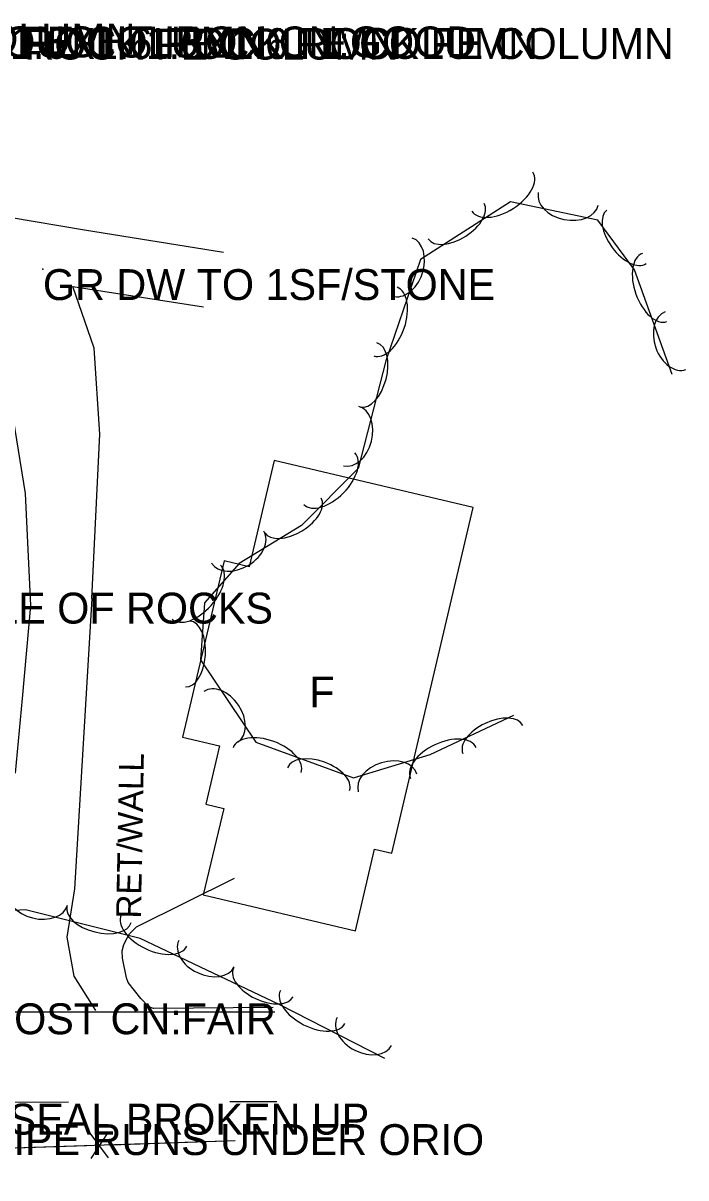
# Model space of a CAD drawing. Extents: x 954793 to 988390, y 1867850 to 1924428.
# Drawn here: x 961164.2 to 961271.4, y 1905548.4 to 1905735.2 of the extents above; entities that cross this region are included whole.
import ezdxf

# ---------------------------------------------------------------- set-up
doc = ezdxf.new("R2010")
doc.units = 0
for name, color, linetype in [('S_BUILDING', 7, 'Continuous'), ('S_BUILDING_ANNOT', 7, 'Continuous'), ('S_DRIVEWAY', 7, 'Continuous'), ('S_FENCE', 7, 'Continuous'), ('S_GRAVEL_ROAD', 7, 'Continuous'), ('S_IRON_PIN_ANNOT', 7, 'Continuous'), ('S_MSC_PT_SYM', 7, 'Continuous'), ('S_SIDE_DRAIN_ANNOT', 7, 'Continuous'), ('S_SURVEY_TEXT_ANNOT', 7, 'Continuous'), ('S_TREE', 7, 'Continuous'), ('S_WALL_ANNOT', 7, 'Continuous')]:
    doc.layers.add(name, color=color, linetype=linetype)

msp = doc.modelspace()

# ---------------------------------------------------------------- linework, layer by layer
at = {"layer": 'S_BUILDING'}
msp.add_lwpolyline([(961223.83, 1905600.9), (961237.02, 1905656.83), (961204.78, 1905664.44), (961200.73, 1905647.26), (961196.7, 1905648.21), (961189.97, 1905619.69), (961195.95, 1905618.28), (961193.73, 1905608.83), (961196.63, 1905608.14), (961193.33, 1905594.15), (961217.95, 1905588.35), (961221.06, 1905601.55)], close=True, dxfattribs=at)
at = {"layer": 'S_DRIVEWAY'}
for points in [[(961196.58, 1905698.09), (961174.09, 1905701.72), (961161.98, 1905703.77), (961149.81, 1905709.09), (961137.67, 1905715.2)], [(961135.97, 1905706.65), (961153.47, 1905696.04), (961160.56, 1905683.46), (961164.51, 1905659.13), (961165.37, 1905640.98), (961164, 1905625.93), (961162.9, 1905613.85)], [(961175.28, 1905642.09), (961175.94, 1905655.4), (961176.61, 1905668.72), (961175.68, 1905682.63), (961172.21, 1905692.58), (961193.35, 1905689.33)], [(961175.28, 1905642.09), (961172.49, 1905595.13), (961171.22, 1905587.33), (961172.38, 1905581.01), (961175.86, 1905575.43)]]:
    msp.add_lwpolyline(points, dxfattribs=at)
at = {"layer": 'S_FENCE'}
for p, q in [((961178, 1905551.6), (961175, 1905555.6)), ((961177.86, 1905555.7), (961175.13, 1905551.51))]:
    msp.add_line(p, q, dxfattribs=at)
for points in [[(961198.49, 1905554.33), (961040.37, 1905549.11)], [(961174.5, 1905553.54), (961154.51, 1905552.88)], [(961198.49, 1905554.33), (961178.5, 1905553.67)]]:
    msp.add_lwpolyline(points, dxfattribs=at)
at = {"layer": 'S_GRAVEL_ROAD'}
for points in [[(961028.96, 1905573.17), (961049.1, 1905571.96), (961076.77, 1905571.9), (961120.25, 1905573.73), (961159.89, 1905575.21), (961204.9, 1905575.25)], [(961205.25, 1905560.69), (961197.61, 1905560.67)], [(961171.5, 1905560.59), (961140.67, 1905560.5), (961110.89, 1905559.04), (961064.17, 1905555.68), (961043.24, 1905554.69), (961020.94, 1905553.02), (961010.77, 1905548.35)]]:
    msp.add_lwpolyline(points, dxfattribs=at)
at = {"layer": 'S_IRON_PIN_ANNOT'}
msp.add_lwpolyline([(961204.64, 1905575.93), (961185.25, 1905575.79), (961184.53, 1905576.03), (961183.22, 1905577.37), (961181.16, 1905579.97), (961180.91, 1905580.71), (961180.26, 1905583.91), (961180.21, 1905585.12), (961180.49, 1905586.11), (961181.04, 1905587.23), (961181.38, 1905587.83), (961181.85, 1905588.34), (961182.52, 1905588.99), (961198.4, 1905596.88)], dxfattribs=at)
at = {"layer": 'S_MSC_PT_SYM'}
for points in [[(961184.01, 1905734.41), (961184.01, 1905734.46), (961184.01, 1905734.41), (961183.96, 1905734.41), (961184.01, 1905734.41), (961184.01, 1905734.36), (961184.01, 1905734.41), (961184.06, 1905734.41)], [(961184.01, 1905734.41), (961184.01, 1905734.46), (961184.01, 1905734.41), (961183.96, 1905734.41), (961184.01, 1905734.41), (961184.01, 1905734.36), (961184.01, 1905734.41), (961184.06, 1905734.41)], [(961167.38, 1905695.41), (961167.38, 1905695.46), (961167.38, 1905695.41), (961167.33, 1905695.41), (961167.38, 1905695.41), (961167.38, 1905695.36), (961167.38, 1905695.41), (961167.43, 1905695.41)], [(961167.38, 1905695.41), (961167.38, 1905695.46), (961167.38, 1905695.41), (961167.33, 1905695.41), (961167.38, 1905695.41), (961167.38, 1905695.36), (961167.38, 1905695.41), (961167.43, 1905695.41)]]:
    msp.add_lwpolyline(points, close=True, dxfattribs=at)
for points in [[(961184.01, 1905734.41), (961184.01, 1905734.46), (961184.01, 1905734.41), (961183.96, 1905734.41), (961184.01, 1905734.41), (961184.01, 1905734.36), (961184.01, 1905734.41), (961184.06, 1905734.41)], [(961167.38, 1905695.41), (961167.38, 1905695.46), (961167.38, 1905695.41), (961167.33, 1905695.41), (961167.38, 1905695.41), (961167.38, 1905695.36), (961167.38, 1905695.41), (961167.43, 1905695.41)]]:
    msp.add_lwpolyline(points, dxfattribs=at)
at = {"layer": 'S_TREE'}
for points in [[(961269.19, 1905678.35), (961263.1, 1905695.31), (961257.16, 1905703.35), (961243.06, 1905706.29), (961228.47, 1905696.99), (961222.87, 1905680.56), (961218.37, 1905663.17), (961209.23, 1905653.92), (961199.14, 1905647.76), (961193.5, 1905641.42), (961192.87, 1905632.2), (961201.82, 1905618.87), (961217.62, 1905613.1), (961230.04, 1905616.85), (961243.6, 1905623.25)], [(961222.72, 1905567.66), (961205.71, 1905576.35), (961183.12, 1905587.1), (961164.56, 1905591.76), (961147.02, 1905590.73)]]:
    msp.add_lwpolyline(points, dxfattribs=at)
for centre, major_axis, ratio in [((961241.73, 1905707.95), (4.95, 3.15), 0.55008), ((961252.39, 1905706.78), (4.85, -1.01), 0.685311), ((961234.25, 1905703.18), (4.51, 2.87), 0.540699), ((961261.8, 1905700.64), (3.18, -4.3), 0.540699), ((961225.54, 1905695.76), (1.6, 4.69), 0.685311), ((961266.38, 1905692.45), (1.98, -5.52), 0.55008), ((961222.8, 1905686.92), (1.89, 5.55), 0.55008), ((961269.76, 1905683.82), (1.68, -4.66), 0.685311), ((961220.1, 1905678.31), (1.34, 5.18), 0.540699), ((961217.26, 1905668.4), (1.24, 4.8), 0.685311), ((961213.72, 1905661.48), (4.12, 4.18), 0.55008), ((961207.84, 1905655.55), (4.56, 2.79), 0.540699), ((961198.91, 1905650.41), (4.23, 2.58), 0.685311), ((961192.19, 1905643.14), (3.9, 4.38), 0.55008), ((961190.8, 1905633.13), (0.37, 5.33), 0.540699), ((961196.2, 1905622.97), (-2.76, 4.11), 0.685311), ((961240.19, 1905619.29), (-4.84, -2.28), 0.540699), ((961203.65, 1905615.94), (-5.51, 2.01), 0.55008), ((961232.17, 1905615.51), (-5.31, -2.5), 0.55008), ((961211.98, 1905612.9), (-5.02, 1.83), 0.540699), ((961223.16, 1905612.28), (-4.74, -1.43), 0.685311), ((961166.53, 1905593.72), (4.81, -1.21), 0.685311), ((961176.46, 1905590.96), (5.19, -1.3), 0.540699), ((961185.36, 1905588.38), (5.3, -2.52), 0.55008), ((961193.83, 1905584.64), (4.48, -2.13), 0.685311), ((961203.03, 1905579.98), (4.83, -2.3), 0.540699), ((961211.03, 1905576.02), (5.22, -2.67), 0.55008), ((961219.39, 1905572.04), (4.41, -2.26), 0.685311)]:
    msp.add_ellipse(centre, major_axis=major_axis, ratio=ratio, start_param=3.141593, end_param=6.283185, dxfattribs=at)

# ---------------------------------------------------------------- texts
at = {"layer": 'S_BUILDING_ANNOT'}
msp.add_text('F', height=5, dxfattribs=at).set_placement((961210.48, 1905624.49))
at = {"layer": 'S_SIDE_DRAIN_ANNOT'}
msp.add_text('CN:5% FILL PIPE RUNS UNDER ORIO', height=5, dxfattribs=at).set_placement((961119.89, 1905552.05))
at = {"layer": 'S_SURVEY_TEXT_ANNOT'}
for s, p in [('1.6X1.6 ROCK FE COLUMN', (961096.88, 1905730.15)), ('1.6X1.6 ROCK FE COLUMN', (961117.82, 1905729.65)), ('FE-4.0 WROUGHT IRON CN:GOOD', (961127.9, 1905729.68)), ('1.6X1.6 ROCK FE COLUMN', (961139.47, 1905729.33)), ('1.6X1.6 ROCK FE COLUMN', (961162.05, 1905729.44)), ('1.6X1.6 ROCK FE COLUMN', (961184.01, 1905729.41)), ('GR DW TO 1SF/STONE', (961167.38, 1905690.41)), ('LARGE PILE OF ROCKS', (961128.81, 1905638.06)), ('FE 3.0 WIRE MET POST CN:FAIR', (961101.42, 1905571.6)), ('CHIP/SEAL BROKEN UP', (961144.01, 1905555.36))]:
    msp.add_text(s, height=5, dxfattribs=at).set_placement(p)
at = {"layer": 'S_WALL_ANNOT'}
msp.add_text('RET/WALL', height=4, rotation=88.9485, dxfattribs=at).set_placement((961183.23, 1905590.3))

doc.saveas('drawing.dxf')
